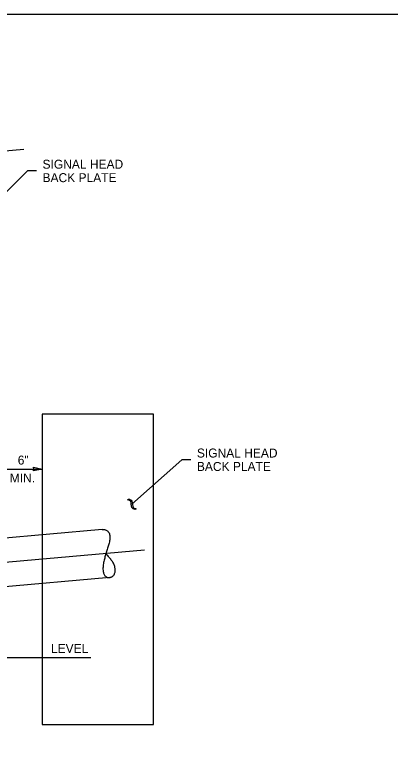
# Model space of a CAD drawing. Extents: x 99862 to 104211, y 98939 to 105076.
# Drawn here: x 101200 to 101870, y 100767 to 102076 of the extents above; entities that cross this region are included whole.
import ezdxf

# ---------------------------------------------------------------- set-up
doc = ezdxf.new("R2010")
doc.units = 0
for name, color, linetype in [('Level 1', 7, 'Continuous'), ('Level 15', 7, 'Continuous'), ('Level 16', 7, 'Continuous'), ('Level 20', 7, 'Continuous'), ('Level 21', 7, 'Continuous')]:
    doc.layers.add(name, color=color, linetype=linetype)

msp = doc.modelspace()

# ---------------------------------------------------------------- linework, layer by layer
at = {"layer": 'Level 1'}
msp.add_lwpolyline([(99862, 99999.5), (103151, 99999.5), (103151, 102075.5), (99862, 102075.5)], close=True, dxfattribs=at)
at = {"layer": 'Level 15'}
for p, q in [((101216.2, 101834.7), (100195.6, 101742.9)), ((101143.8, 101717.6), (101222.8, 101796.4)), ((101238.8, 101796.4), (101222.8, 101796.4)), ((101409, 101201.1), (101498.1, 101280.6)), ((101514.1, 101280.6), (101498.1, 101280.6)), ((101183.5, 101264), (101249.1, 101264)), ((101401, 101209.1), (101402.9, 101210.1)), ((101403.4, 101208.5), (101401, 101209.1)), ((101402.9, 101210.1), (101404.8, 101209.9)), ((101405, 101207.9), (101403.4, 101208.5)), ((101404.8, 101209.9), (101406.5, 101209.2)), ((101406.1, 101207.1), (101405, 101207.9)), ((101406.9, 101206.1), (101406.1, 101207.1)), ((101406.5, 101209.2), (101407.9, 101208.2)), ((101407.6, 101204.3), (101406.9, 101206.1)), ((101407.8, 101201.7), (101407.6, 101204.3)), ((101407.9, 101208.2), (101409, 101206.8)), ((101409, 101206.8), (101409.9, 101204.3)), ((101409.9, 101204.3), (101410.3, 101199.9)), ((101408.1, 101197.6), (101407.8, 101201.7)), ((101409, 101195.3), (101408.1, 101197.6)), ((101410, 101194), (101409, 101195.3)), ((101411.3, 101193), (101410, 101194)), ((101410.3, 101199.9), (101410.5, 101197.4)), ((101410.5, 101197.4), (101411, 101196)), ((101411, 101196), (101411.9, 101195)), ((101412.9, 101192.4), (101411.3, 101193)), ((101411.9, 101195), (101413.3, 101194.1)), ((101415, 101192), (101412.9, 101192.4)), ((101413.3, 101194.1), (101416.9, 101193.1)), ((101416.9, 101193.1), (101415, 101192)), ((101431.2, 101119.2), (100196.5, 101010)), ((101180.9, 100927.7), (101335.9, 100927.7))]:
    msp.add_line(p, q, dxfattribs=at)
msp.add_lwpolyline([(101249.1, 101264), (101233.4, 101260.9), (101234.1, 101264), (101233.4, 101267.1)], close=True, dxfattribs=at)
at = {"layer": 'Level 16'}
for p, q in [((101356.1, 101156.1), (101055.3, 101129.4)), ((101369.5, 101070.2), (101062.3, 101043))]:
    msp.add_line(p, q, dxfattribs=at)
msp.add_lwpolyline([(101379.1, 101084.6), (101378.3, 101089.8)], dxfattribs=at)
for points in [[(101356.1, 101156.1), (101356.4, 101156.1), (101357.2, 101156.2), (101358.6, 101156.2), (101360.4, 101155.9), (101362.2, 101155.3), (101364, 101154.4), (101365.8, 101153), (101367.5, 101151.1), (101368.9, 101148.6), (101369.5, 101146.5), (101369.7, 101145.3)], [(101369.7, 101145.3), (101369.9, 101144.1), (101370, 101141.6), (101369.6, 101137.7), (101368.8, 101133.8), (101367.8, 101130), (101366.8, 101126.2), (101365.6, 101122.4), (101364.5, 101118.6), (101363.3, 101114.8), (101362.1, 101110.9), (101361, 101107.1), (101359.9, 101103.1), (101359, 101099.1), (101358.2, 101095.1), (101357.6, 101090.9), (101357.3, 101086.9), (101357.4, 101082.9), (101358, 101079.4), (101358.9, 101076.5), (101360.2, 101074.2), (101361.8, 101072.4), (101363.4, 101071.3), (101365, 101070.5), (101366.8, 101070.1), (101368.5, 101070), (101370.2, 101070.3), (101371.9, 101070.9), (101373.5, 101071.7), (101375, 101072.8), (101376.5, 101074.3), (101377.7, 101076.1), (101378.8, 101078.4), (101379.4, 101081.2), (101379.3, 101083.4), (101379.1, 101084.6)], [(101378.3, 101090.1), (101378.1, 101091.1), (101377.5, 101093.1), (101376, 101096), (101374.2, 101098.8), (101372.2, 101101.5), (101370.2, 101104.2), (101368.1, 101106.8), (101365.9, 101109.4), (101364.1, 101111.5), (101363.1, 101112.8), (101362.8, 101113.1)]]:
    msp.add_open_spline(points, degree=3, dxfattribs=at)
at = {"layer": 'Level 21'}
msp.add_line((101249.1, 101146.7), (101249.1, 101059.6), dxfattribs=at)
for points in [[(101249.1, 101059.6), (101249.1, 100807.6), (101447.5, 100807.6), (101447.5, 101362.1), (101249.1, 101362.1)], [(101249.1, 101362.1), (101249.1, 101146.7)]]:
    msp.add_lwpolyline(points, dxfattribs=at)

# ---------------------------------------------------------------- texts
at = {"layer": 'Level 20'}
for s, p in [('SIGNAL HEAD', (101249.6, 101800.4)), ('BACK PLATE', (101249.6, 101776.4)), ('SIGNAL HEAD', (101524.9, 101284.6)), ('6"', (101205.4, 101272)), ('BACK PLATE', (101524.9, 101260.6)), ('MIN.', (101191.2, 101240)), ('LEVEL', (101264.6, 100935.7))]:
    msp.add_text(s, height=16, dxfattribs=at).set_placement(p)

doc.saveas('drawing.dxf')
